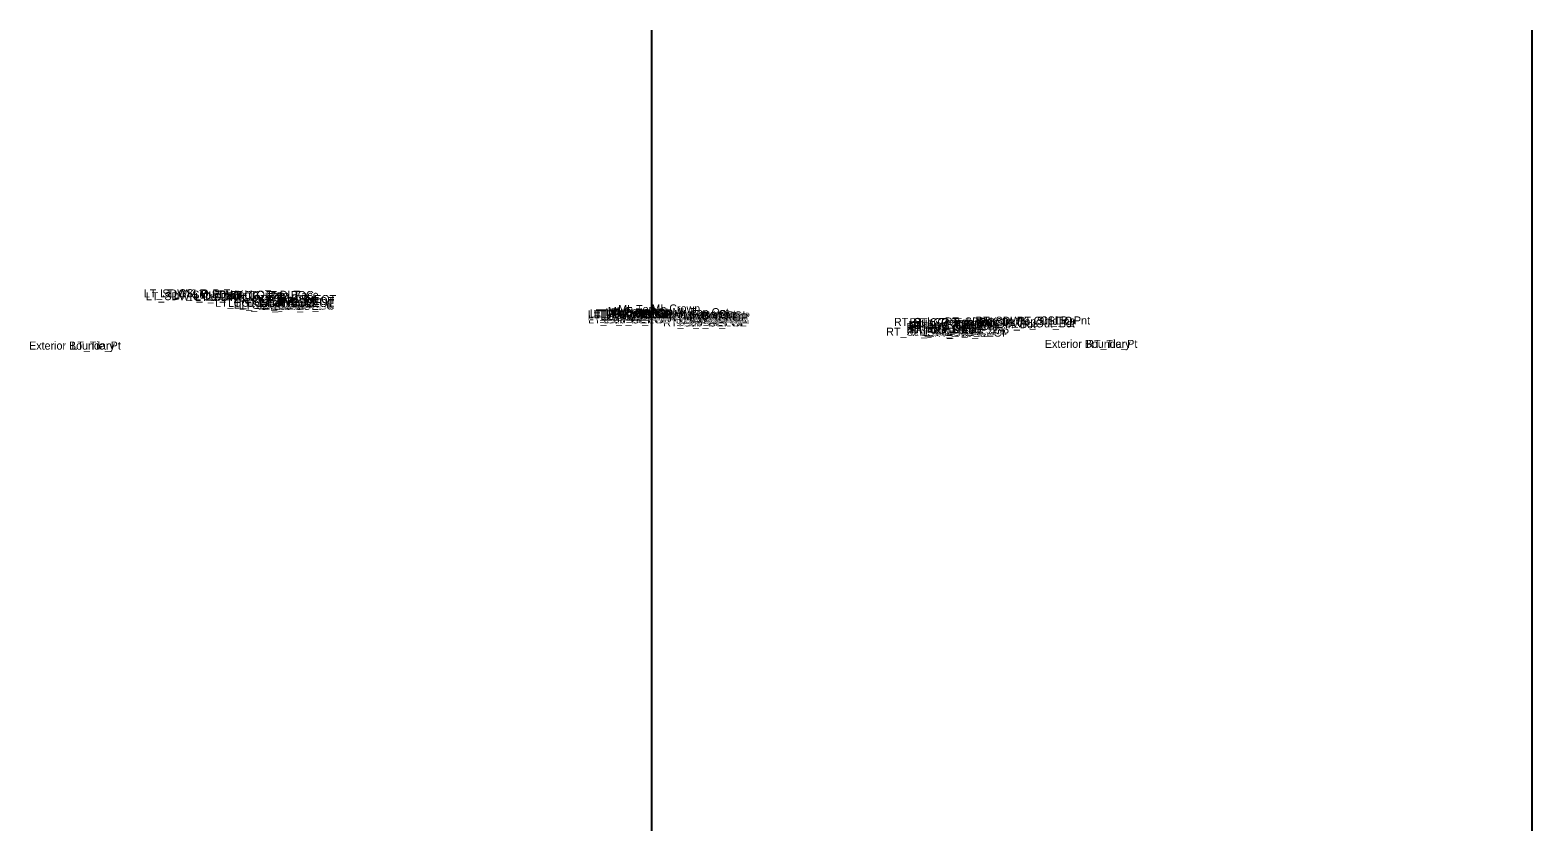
# Model space of a CAD drawing. Extents: x 0 to 6300, y -50 to 9550.
# Drawn here: x 1072.4 to 1260, y 5450 to 5550 of the extents above; entities that cross this region are included whole.
import ezdxf

# ---------------------------------------------------------------- set-up
doc = ezdxf.new("R2010")
doc.units = 0
for name, color, linetype in [('Default', 7, 'Continuous'), ('Prop XS Exc Vertical Line 2', 7, 'Continuous'), ('Prop XS Exc Vertical Line 3', 7, 'Continuous')]:
    doc.layers.add(name, color=color, linetype=linetype)

msp = doc.modelspace()

# ---------------------------------------------------------------- linework, layer by layer
at = {"layer": 'Prop XS Exc Vertical Line 2'}
msp.add_line((1150, 5550), (1150, 5450), dxfattribs=at)
at = {"layer": 'Prop XS Exc Vertical Line 3'}
msp.add_line((1260, 5550), (1260, 5450), dxfattribs=at)

# ---------------------------------------------------------------- texts
at = {"layer": 'Default'}
for s, p in [('LT_SDWK_Out_Top', (1086.58, 5516.61)), ('LT_SDWK_Out_Bot', (1086.83, 5516.27)), ('LT_CSLP_Pnt', (1088.6, 5516.64)), ('LT_Sub_Trench_Out_DLT', (1090.32, 5516.46)), ('LT_SDWK_In_Top', (1092.74, 5516.51)), ('LT_SDWK_In_Bot', (1092.99, 5516.17)), ('LT_CG_Top_BOC', (1096.81, 5516.42)), ('LT_CG_Top_Face', (1097.34, 5516.42)), ('LT_CG_Top_Gut', (1097.87, 5515.92)), ('LT_PV1_OEOT', (1101.23, 5515.92)), ('LT_CG1_Shelf_Out', (1095.48, 5515.45)), ('LT_CG_Bot_BOC', (1097.09, 5515.43)), ('LT_Sub_OEOP', (1097.79, 5515.21)), ('LT_Sub_OEOT_CG', (1098.44, 5515.08)), ('LT_PV2_OEOT', (1100.99, 5515.67)), ('LT_PV3_OEOT', (1100.99, 5515.42)), ('LT_Sub_OEOT', (1101.04, 5515.04)), ('LT_CG_Bot_IE', (1101.34, 5515.33)), ('LT_PV2_OEEOP', (1142.04, 5514)), ('LT_PV1_OEEOP', (1142.27, 5514.12)), ('LT_PV2_IEEOP', (1142.8, 5514)), ('LT_PV1_IEEOP', (1143.04, 5514.12)), ('LT_PV2_PGL1', (1143.63, 5514)), ('LT_PV2_PGL', (1144.01, 5514)), ('LT_PV1_PGL', (1144.25, 5514.25)), ('MI_Face In', (1144.55, 5514.41)), ('MI_Bot In', (1145.72, 5514.25)), ('MI_Top In', (1145.84, 5514.66)), ('MI_Crown', (1149.99, 5514.74)), ('MI_Top Out', (1152.6, 5514.28)), ('MI_Face Out', (1152.81, 5514.03)), ('LT_PV3_OEEOP', (1142.04, 5513.75)), ('LT_Sub_OEEOP', (1142.08, 5513.37)), ('LT_PV3_PGL1', (1143.63, 5513.75)), ('LT_PV4_PGL', (1144.01, 5513.37)), ('RT_PV2_OEEOP', (1151.42, 5513.62)), ('RT_PV3_OEEOP', (1151.42, 5513.37)), ('RT_Sub_OEEOP', (1151.46, 5512.99)), ('RT_PV1_OEEOP', (1151.66, 5513.74)), ('RT_PV2_IEEOP', (1152.18, 5513.62)), ('RT_PV1_IEEOP', (1152.42, 5513.74)), ('RT_PV2_PGL1', (1153.02, 5513.62)), ('RT_PV3_PGL1', (1153.02, 5513.37)), ('RT_PV2_PGL', (1153.4, 5513.62)), ('RT_PV4_PGL', (1153.4, 5512.99)), ('RT_PV1_PGL', (1153.63, 5513.87)), ('MI_Bot Out', (1154, 5513.87)), ('RT_Sub_Trench_Out_DLT', (1180.29, 5513.06)), ('RT_PV2_OEOT', (1181.87, 5512.43)), ('RT_PV3_OEOT', (1181.87, 5512.18)), ('RT_PV1_OEOT', (1182.11, 5512.68)), ('RT_CG_Top_Face', (1182.22, 5513.02)), ('RT_CG_Bot_IE', (1182.22, 5512.09)), ('RT_CG_Top_BOC', (1182.69, 5513.02)), ('RT_CG_Top_Gut', (1182.75, 5512.52)), ('RT_SDWK_In_Top', (1186.62, 5513.11)), ('RT_SDWK_In_Bot', (1186.87, 5512.77)), ('RT_SDWK_Out_Top', (1190.46, 5513.21)), ('RT_SDWK_Out_Bot', (1190.71, 5512.87)), ('RT_Shld_O', (1195.63, 5513.2)), ('CSLP_Pnt', (1198.54, 5513.24)), ('RT_Sub_OEOT_CG', (1179.32, 5511.84)), ('RT_Sub_OEOT', (1181.92, 5511.8)), ('RT_CG1_Shelf_Out', (1182.36, 5511.97)), ('RT_CG_Bot_BOC', (1182.97, 5511.99)), ('RT_Sub_OEOP', (1185.17, 5511.71)), ('Exterior Boundary', (1199.15, 5510.32)), ('RT_Tie_Pt', (1204.31, 5510.32)), ('Exterior Boundary', (1072.24, 5510.1)), ('LT_Tie_Pt', (1077.52, 5510.1))]:
    msp.add_text(s, height=1, dxfattribs=at).set_placement(p)

doc.saveas('drawing.dxf')
